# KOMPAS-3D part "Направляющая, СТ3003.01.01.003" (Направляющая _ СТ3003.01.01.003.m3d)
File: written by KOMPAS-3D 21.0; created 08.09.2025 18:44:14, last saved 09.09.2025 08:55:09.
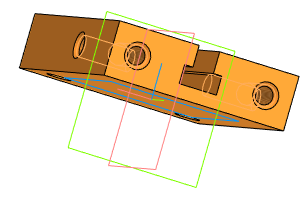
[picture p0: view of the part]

Document properties: Полное имя файла: C:\Users\1\Yandex.Disk\Документы\Новая папка\Стапель №2\Стапель _ СТ3003.00.00.000\Опора _ СТ3003.01.00.000\3D\Кронштейн _ СТ3003.01.01.000\Направляющая _ СТ3003.01.01.003.m3d

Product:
- Part/product: Направляющая  | designation СТ3003.01.01.003
    Материал: Сталь 45  ГОСТ 1050-2013 (density 7810 kg/m3)
    Масса: 0.806848
    Форматы листов документа: A3

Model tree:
1. Эскиз:1
2. Элемент выдавливания:1
     Расстояние 1 = 90
3. Эскиз:2  (with: Элемент выдавливания:1)
4. Элемент выдавливания:2
     Расстояние 2 = 20
5. Эскиз:3  (with: Элемент выдавливания:1, Элемент выдавливания:2)
6. Элемент выдавливания:3
     Расстояние 2 = 10
7. Эскиз:5  (with: Элемент выдавливания:1)
8. ЛСК:2  (with: Плоскость XY, Плоскость ZX, Плоскость ZY, Ось X, Ось Y, Ось Z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)
     Ось X. X = 1; Ось Y. Y = 1; Ось Z. Z = 1; Координата X = 35; Координата Y = 10; Координата Z = 10; Точка начала. Х = 35; Точка начала. Y = 10; Точка начала. Z = 10
9. Эскиз:6
10. Элемент вращения:1
     Угол 1 = 360
11. Смещенная плоскость:1  (with: Элемент выдавливания:1)
     Расстояние = 0.923418
12. Условное изображение резьбы:1  (with: Элемент вращения:1)  (labels: 8x1,25)
     Длина резьбы = 19.0766; Шаг резьбы = 1.25; Номинальный диаметр резьбы = 8
13. Подгонка:1
14. Отверстие М8x20/1,6x45°
15. Эскиз:9  (with: Элемент выдавливания:1)
16. ЛСК:5  (with: Плоскость XY, Плоскость ZX, Плоскость ZY, Ось X, Ось Y, Ось Z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)
     Ось X. X = -1; Ось Y. Y = 1; Ось Z. Z = -1; Координата X = -35; Координата Y = 10; Координата Z = 10; Точка начала. Х = -35; Точка начала. Y = 10; Точка начала. Z = 10
17. Эскиз:10
18. Элемент вращения:2
     Угол 1 = 360
19. Смещенная плоскость:2  (with: Элемент выдавливания:1)
     Расстояние = 0.923418
20. Условное изображение резьбы:2  (with: Элемент вращения:2)  (labels: 8x1,25)
     Длина резьбы = 19.0766; Шаг резьбы = 1.25; Номинальный диаметр резьбы = 8
21. Подгонка:2
22. Отверстие М8x20/1,6x45° (1)
23. Эскиз:13  (with: Элемент выдавливания:1)
24. ЛСК:8  (with: Плоскость XY, Плоскость ZX, Плоскость ZY, Ось X, Ось Y, Ось Z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)
     Ось X. Y = 1; Ось Y. X = -1; Ось Z. Z = 1; Координата X = 25; Координата Y = 45; Координата Z = 10; Точка начала. Х = 25; Точка начала. Y = 45; Точка начала. Z = 10
25. Эскиз:14
26. Элемент вращения:3
     Угол 1 = 360
27. Смещенная плоскость:3  (with: Элемент выдавливания:1)
     Расстояние = 0.923418
28. Условное изображение резьбы:3  (with: Элемент вращения:3)  (labels: 8x1,25)
     Длина резьбы = 19.0766; Шаг резьбы = 1.25; Номинальный диаметр резьбы = 8
29. Подгонка:3
30. Отверстие М8x20/1,6x45° (2)
31. Эскиз:16  (with: Элемент выдавливания:1)
32. ЛСК:10  (with: Плоскость XY, Плоскость ZX, Плоскость ZY, Ось X, Ось Y, Ось Z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)
     Ось X. Y = 1; Ось Y. X = 1; Ось Z. Z = -1; Координата X = -25; Координата Y = 45; Координата Z = 10; Точка начала. Х = -25; Точка начала. Y = 45; Точка начала. Z = 10
33. Эскиз:17
34. Элемент вращения:4
     Угол 1 = 360
35. Смещенная плоскость:4  (with: Элемент выдавливания:1)
     Расстояние = 0.923418
36. Условное изображение резьбы:4  (with: Элемент вращения:4)  (labels: 8x1,25)
     Длина резьбы = 19.0766; Шаг резьбы = 1.25; Номинальный диаметр резьбы = 8
37. Подгонка:4
38. Отверстие М8x20/1,6x45° (3)  (labels: Сталь 45  ГОСТ 1050-2013)

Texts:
  KTE.LIST=LTWD36N5dmSErgwNQxupvb
  Edge1
  Edge2
  СТ3003.01.01.003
